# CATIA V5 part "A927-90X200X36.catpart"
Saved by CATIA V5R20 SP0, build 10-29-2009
Part number: A927-90X200X36
Source: Unknown
Property "A": "50.000"
Property "ARTICLENO": "A927-90X200X36"
Property "BOMINFO": "A927-90X200X36"
Property "CODE": "A927-90X200X36"
Property "CREATOR": "CADENAS GmbH"
Property "D": "18.000"
Property "D1": "26.000"
Property "F": "28.000"
Property "FORM": "A"
Property "L": "200.000"
Property "L1": "100.000"
Property "L2": "20.000"
Property "L3": "50.000"
Property "LINA": "A927-90X200X36"
Property "NB": "A927-90X200X36"
Property "NBSYN": "$CODE."
Property "NN": "A927"
Property "NT": "VDI 3387 Removable Die Heels, steel and self-lubricating"
Property "R": "25.000"
Property "S": "36.000"
Property "SUPPLIER": "CF"
Property "T": "21.000"
Property "W": "90.000"
Bounding box of the stored display mesh (mm): x -45 to 45, y 0 to 200, z -36 to 0
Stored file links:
  C:\Users\borellobunino\Desktop\3D X SITO CF\A927\GSB_OILLESS_G2290509020036\CATIAV5\A927-90X200X36.catpart
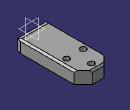
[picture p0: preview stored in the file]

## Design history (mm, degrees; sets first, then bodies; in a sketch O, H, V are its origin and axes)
Body1 "Geometry.1" (main body)
  Solid1 "A927-90X200X36.catpart": solid without history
